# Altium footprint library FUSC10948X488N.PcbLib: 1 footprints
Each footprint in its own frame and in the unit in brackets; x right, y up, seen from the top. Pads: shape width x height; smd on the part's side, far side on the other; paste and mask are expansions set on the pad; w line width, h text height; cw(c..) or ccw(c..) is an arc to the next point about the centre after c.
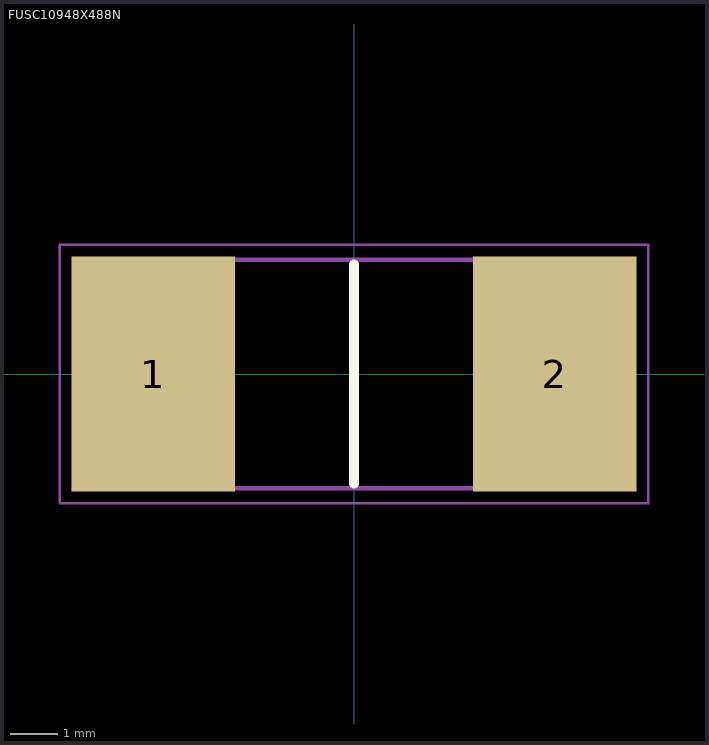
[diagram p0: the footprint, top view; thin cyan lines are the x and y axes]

## FUSC10948X488N [mm]
pads (2):
  rect 3.41x4.91 smd: 1(-4.195,0) 2(4.195,0)
Top Overlay:
  lines w0.2: 0,-2.29 0,2.29
Mechanical 15:
  lines w0.1: -5.43,-2.39 5.43,-2.39 5.43,2.39 -5.43,2.39 -5.43,-2.39
Mechanical 20:
  lines w0.05: -6.15,-2.705 6.15,-2.705 6.15,2.705 -6.15,2.705 -6.15,-2.705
